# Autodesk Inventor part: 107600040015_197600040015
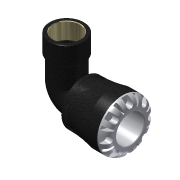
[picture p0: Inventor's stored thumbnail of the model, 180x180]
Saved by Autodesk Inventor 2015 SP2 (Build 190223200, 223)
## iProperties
Created: 2016-12
Part Number: 107600040015_197600040015
Material: PVC-Piping
Description: PLASSON 90° ELBOW WITH FEMALE INTEGRAL BRASS 40X1.1/2" SERIES 1
Document SubType Name: Modeling
Designer: KIM
Mass: 664.223 g
Surface Area: 733.008 cm^2
Volume: 474.445 cm^3
Density: 1.4 g/cm^3
Appearance: Black Cast
Author: KIM
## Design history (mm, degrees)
derived "1076.ipt"
feature "Solid1::1076.ipt"
tag "TaggingFeature1"
body "Solid1"
other parameters: "d1" = 30.24, "d8" = 61.6, "d13" = 8, "d14" = 8, "d15" = 0, "d17" = 360 deg, "d19" = 8 deg, "d20" = 0.8, "d21" = 0.8, "d22" = 8 deg, "d24" = 0, "d26" = 360 deg, "d33" = 7, "d51" = 0.7, "d54" = 14, "d55" = 8.8, "d57" = 15.68, "d58" = 0, "d74" = 0, "d78" = 72, "d82" = 0.8, "d115" = 360 deg, "d207" = 90 deg, "d228" = 11.9, "d248" = 4.32, "d270" = 107, "d281" = 6.72675, "d294" = 44.845, "d295" = 21, "d296" = 23.1, "d297" = 40.3605, "d299" = 52.46865, "d300" = 40.3605, "d301" = 0, "d302" = 0, "d306" = 2.91492, "d309" = 72.72, "d310" = 4.56568, "d312" = 15 deg, "d313" = 0.56, "d314" = 5.184, "d315" = 0.35, "l_" = 72, "A_" = 107, "l_2" = 21, "Rp_" = 44.845, "d9" = 10, "d298" = 58.2985
